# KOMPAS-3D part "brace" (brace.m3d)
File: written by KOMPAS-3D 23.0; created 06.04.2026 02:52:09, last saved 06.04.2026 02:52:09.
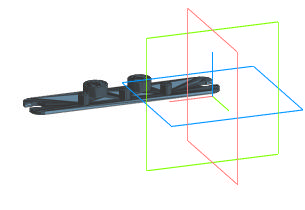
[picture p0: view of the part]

Document properties: Автор: Стас; Полное имя файла: C:\Users\Стас\Desktop\Tank Tread - 332816\files\brace.m3d

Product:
- Part/product: brace

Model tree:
1. Полигональный объект:1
